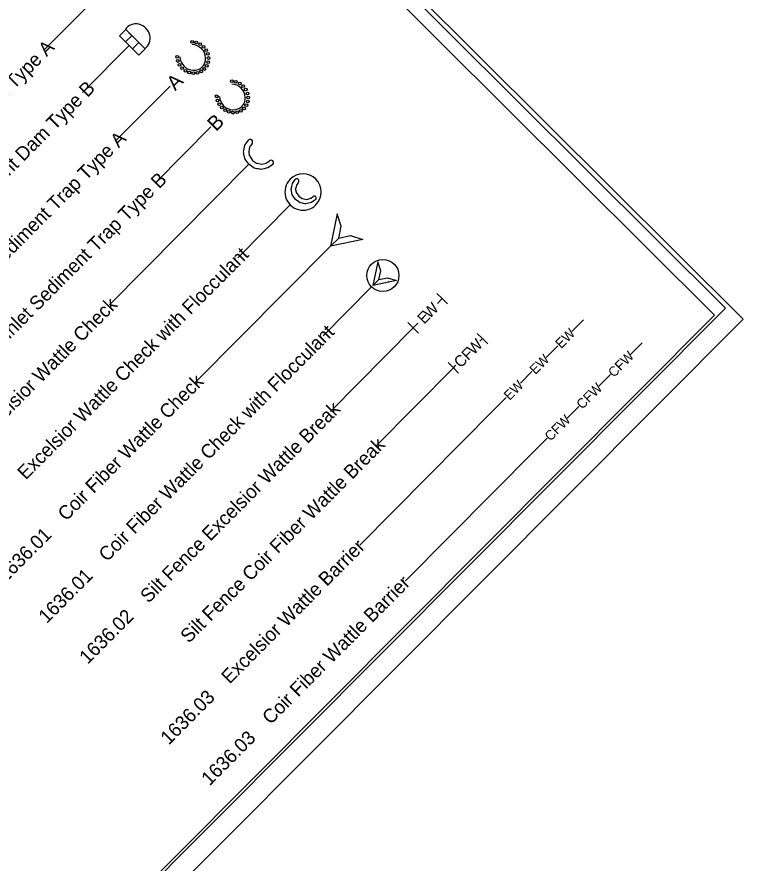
# Model space of a CAD drawing. Extents: x 1489771 to 1495672, y 500348 to 506262.
# Drawn here: x 1493531 to 1495672, y 502337 to 504832 of the extents above; entities that cross this region are included whole.
import ezdxf

# ---------------------------------------------------------------- set-up
doc = ezdxf.new("R2010")
doc.units = 0
for name, color, linetype in [('Old_Level_1', 7, 'Continuous'), ('Old_Level_12', 7, 'Continuous'), ('Sheet Plot Border Inside CELL', 7, 'Continuous')]:
    doc.layers.add(name, color=color, linetype=linetype)

msp = doc.modelspace()

# ---------------------------------------------------------------- linework, layer by layer
at = {"layer": 'Old_Level_1'}
for p, q in [((1493610.4, 504733.7), (1493742.9, 504867.2)), ((1493890.8, 504719.4), (1493833.7, 504776.3)), ((1493890.8, 504719.4), (1493833.7, 504776.3)), ((1493909.1, 504737.8), (1493852, 504794.7)), ((1493909.1, 504737.8), (1493852, 504794.7)), ((1493725, 504609.7), (1493862.2, 504747.8)), ((1493909.1, 504737.8), (1493890.8, 504719.4)), ((1493909.1, 504737.8), (1493890.8, 504719.4)), ((1493821.4, 504465.3), (1493982.8, 504627.8)), ((1493940.9, 504344.2), (1494103.3, 504507.7)), ((1494219.9, 504452.2), (1494217.4, 504448.6)), ((1494224.8, 504459.2), (1494219.9, 504452.2)), ((1494216.2, 504442.6), (1494214.6, 504434.7)), ((1494214.9, 504433.4), (1494214.6, 504434.7)), ((1494214.9, 504433.4), (1494216.3, 504427.5)), ((1494217.4, 504448.6), (1494216.2, 504442.6)), ((1494217.8, 504421), (1494216.3, 504427.5)), ((1494217.8, 504421), (1494226.2, 504409.1)), ((1494226.2, 504409.1), (1494226.2, 504409.1)), ((1494226.2, 504409.1), (1494237.7, 504401)), ((1494267.1, 504401.7), (1494275.6, 504407.5)), ((1493803.8, 503983.3), (1494214.6, 504397.5)), ((1494237.7, 504401), (1494244.2, 504399.5)), ((1494244.2, 504399.5), (1494252, 504397.7)), ((1494252, 504397.7), (1494257.6, 504398.9)), ((1494257.6, 504398.9), (1494265.6, 504400.6)), ((1494267.1, 504401.7), (1494265.6, 504400.6)), ((1494354, 504331.2), (1494352.7, 504324.7)), ((1494355, 504336.2), (1494354, 504331.2)), ((1494357.1, 504339.2), (1494355, 504336.2)), ((1494361.2, 504345.1), (1494357.1, 504339.2)), ((1494352.9, 504323.6), (1494352.7, 504324.7)), ((1494352.9, 504323.6), (1494354.1, 504318.6)), ((1494355.4, 504313.3), (1494354.1, 504318.6)), ((1494355.4, 504313.3), (1494362.4, 504303.3)), ((1494362.4, 504303.3), (1494362.4, 504303.3)), ((1494362.4, 504303.3), (1494372, 504296.5)), ((1494182.2, 504121.2), (1494337, 504277.7)), ((1494372, 504296.5), (1494377.4, 504295.2)), ((1494377.4, 504295.2), (1494383.9, 504293.7)), ((1494383.9, 504293.7), (1494388.5, 504294.8)), ((1494388.5, 504294.8), (1494395.2, 504296.2)), ((1494396.5, 504297.1), (1494395.2, 504296.2)), ((1494396.5, 504297.1), (1494403.6, 504301.9)), ((1494475.4, 504242.5), (1494475.4, 504242.5)), ((1494056.9, 503754.4), (1494456, 504155.9)), ((1494595, 504103.5), (1494595, 504103.5)), ((1494434, 503892), (1494576.6, 504035.9)), ((1494627.5, 504052.5), (1494626.5, 504051.8)), ((1494784.8, 504001.3), (1494769.3, 504016.8)), ((1494770.9, 503987.3), (1494784.8, 504001.3)), ((1494784.8, 504001.3), (1494800.4, 503985.8)), ((1494699.3, 503915.4), (1494683.7, 503930.9)), ((1494699.3, 503915.4), (1494713.2, 503929.4)), ((1495167.6, 503904.4), (1495201.7, 503938.8)), ((1494455.3, 503668.3), (1494699.3, 503915.4)), ((1494699.3, 503915.4), (1494714.8, 503899.9)), ((1494903.5, 503883.3), (1494887.9, 503898.8)), ((1494895.7, 503875.5), (1494903.5, 503883.3)), ((1494903.5, 503883.3), (1494919.1, 503867.8)), ((1495091.5, 503828), (1495125.7, 503862.3)), ((1495340.4, 503836.9), (1495374.6, 503871.3)), ((1494817.9, 503797.3), (1494802.3, 503812.8)), ((1494817.9, 503797.3), (1494825.6, 503805.1)), ((1494588.2, 503565.5), (1494817.9, 503797.3)), ((1494817.9, 503797.3), (1494833.5, 503781.8)), ((1495015.5, 503751.5), (1495049.6, 503785.9)), ((1495247, 503742.9), (1495281.1, 503777.3)), ((1494939.4, 503675.1), (1494973.6, 503709.5)), ((1495153.5, 503649), (1495187.6, 503683.4)), ((1494541.7, 503274.6), (1494939.4, 503675.1)), ((1495060, 503555), (1495094.2, 503589.4)), ((1494676.6, 503169.1), (1495060, 503555))]:
    msp.add_line(p, q, dxfattribs=at)
for points in [[(1493352.5, 506178.3), (1490172.1, 502984.8), (1492407.6, 500758.5), (1495587.9, 503952.1)], [(1493833.7, 504776.3), (1493852, 504794.7), (1493870, 504776.7), (1493851.7, 504758.3)], [(1493872.1, 504738), (1493890.5, 504756.4), (1493909.1, 504737.8), (1493890.8, 504719.4)], [(1494475.4, 504251.3), (1494456, 504155.9), (1494480, 504180), (1494487.3, 504214.6)], [(1494551.3, 504175.7), (1494456, 504155.9), (1494480, 504180), (1494514.6, 504187.4)], [(1494595, 504109.9), (1494580.8, 504040), (1494598.4, 504057.6), (1494603.7, 504083)], [(1494650.7, 504054.4), (1494580.8, 504040), (1494598.4, 504057.6), (1494623.7, 504063.1)]]:
    msp.add_lwpolyline(points, close=True, dxfattribs=at)
for points in [[(1494285.7, 504397.3), (1494278.7, 504392.4), (1494270.5, 504386.6), (1494266, 504385.6), (1494260.5, 504384.4), (1494250.8, 504382.2), (1494250.6, 504382.2), (1494248.2, 504382.7), (1494247.8, 504382.8), (1494242.6, 504383.9), (1494239, 504384.6), (1494231.1, 504386.3), (1494226.3, 504389.5), (1494214.6, 504397.4), (1494214.6, 504397.5), (1494206.4, 504409.5), (1494203.2, 504414.2), (1494201.9, 504420.4), (1494201.6, 504421.7), (1494200.6, 504426.9), (1494199.8, 504430.8), (1494199.6, 504431.8), (1494199.2, 504433.7), (1494199.2, 504433.8), (1494200.9, 504442), (1494202.5, 504449.2), (1494203.4, 504453.6), (1494208.8, 504461.7), (1494213.6, 504468.8)], [(1494412.1, 504293.5), (1494406.2, 504289.3), (1494399.3, 504284.5), (1494395.6, 504283.6), (1494391, 504282.6), (1494382.9, 504280.8), (1494382.7, 504280.9), (1494380.7, 504281.3), (1494380.4, 504281.3), (1494376.1, 504282.2), (1494373.1, 504282.9), (1494366.4, 504284.3), (1494362.5, 504286.9), (1494352.7, 504293.6), (1494352.7, 504293.6), (1494345.8, 504303.6), (1494343.1, 504307.6), (1494342.1, 504312.7), (1494341.9, 504313.8), (1494341, 504318.1), (1494340.3, 504321.4), (1494340.1, 504322.2), (1494339.8, 504323.8), (1494339.8, 504323.9), (1494341.3, 504330.7), (1494342.6, 504336.8), (1494343.3, 504340.4), (1494347.9, 504347.2), (1494351.8, 504353.1)]]:
    msp.add_lwpolyline(points, dxfattribs=at)
msp.add_circle((1494610.1, 504069.5), 47.4, dxfattribs=at)
for centre, radius, start, end in [((1494218.8, 504463.6), 7.38, 324.006, 135.1186), ((1494280.7, 504402.4), 7.18, 315.1186, 135.1186), ((1494374.8, 504315.7), 53.6, 135.1186, 315.1186), ((1494374.8, 504315.7), 53.6, 315.1186, 135.1186), ((1494356.2, 504348.7), 6.16, 324.006, 135.1186), ((1494407.8, 504297.7), 5.99, 315.1186, 135.1186)]:
    msp.add_arc(centre, radius, start, end, dxfattribs=at)
for centre, major_axis, start_param, end_param in [((1493884.8, 504771.8), (-29.1, 29), 2.949905, 6.474869), ((1493884.8, 504771.8), (-29.1, 29), 2.949905, 6.474869), ((1494049.7, 504712.6), (-27.9, 27.8), 0.785389, 5.497624), ((1494166.5, 504596.2), (-27.9, 27.8), 0.785389, 5.497624)]:
    msp.add_ellipse(centre, major_axis=major_axis, ratio=0.927398, start_param=start_param, end_param=end_param, dxfattribs=at)
for centre, major_axis in [((1494047.9, 504758.9), (-3.01, 3)), ((1494059.9, 504756.9), (-3.01, 3)), ((1494071.3, 504751.8), (-3.01, 3)), ((1494081.1, 504744.2), (-3.01, 3)), ((1494088.9, 504734.3), (-3.01, 3)), ((1494093.9, 504723), (-3.01, 3)), ((1494003.4, 504714.2), (3.01, -3)), ((1494005.4, 504702.2), (3.01, -3)), ((1494094.9, 504699), (3.01, -3)), ((1494096, 504710.9), (-3.01, 3)), ((1494010.5, 504690.9), (3.01, -3)), ((1494018.2, 504681), (3.01, -3)), ((1494028.1, 504673.3), (3.01, -3)), ((1494083.7, 504678.7), (3.01, -3)), ((1494090.7, 504688), (3.01, -3)), ((1494039.5, 504668.3), (3.01, -3)), ((1494051.5, 504666.3), (3.01, -3)), ((1494063.4, 504667.4), (3.01, -3)), ((1494074.4, 504671.7), (3.01, -3)), ((1494164.7, 504642.5), (-3.01, 3)), ((1494176.7, 504640.5), (-3.01, 3)), ((1494188.1, 504635.5), (-3.01, 3)), ((1494198, 504627.8), (-3.01, 3)), ((1494120.2, 504597.9), (3.01, -3)), ((1494205.7, 504617.9), (-3.01, 3)), ((1494210.8, 504606.6), (-3.01, 3)), ((1494122.3, 504585.8), (3.01, -3)), ((1494127.4, 504574.5), (3.01, -3)), ((1494211.7, 504582.6), (3.01, -3)), ((1494212.8, 504594.6), (-3.01, 3)), ((1494135.1, 504564.7), (3.01, -3)), ((1494145, 504557), (3.01, -3)), ((1494156.3, 504551.9), (3.01, -3)), ((1494168.4, 504549.9), (3.01, -3)), ((1494180.3, 504551.1), (3.01, -3)), ((1494191.3, 504555.3), (3.01, -3)), ((1494200.6, 504562.3), (3.01, -3)), ((1494207.6, 504571.6), (3.01, -3))]:
    msp.add_ellipse(centre, major_axis=major_axis, ratio=0.927398, dxfattribs=at)
at = {"layer": 'Old_Level_12'}
msp.add_lwpolyline([(1492102.5, 500356.3), (1495671.9, 503940.6), (1493340.6, 506262.2), (1489771.2, 502678)], close=True, dxfattribs=at)
at = {"layer": 'Sheet Plot Border Inside CELL'}
msp.add_lwpolyline([(1492087.5, 500426.4), (1495619.8, 503973.4), (1493373.6, 506210.2), (1489841.3, 502663.3)], close=True, dxfattribs=at)

# ---------------------------------------------------------------- texts
at = {"layer": 'Old_Level_1'}
for s, height, p in [('Temporary Rock Sediment Dam Type A', 40.777, (1492962.4, 504054.1)), ('A', 42.9, (1493998, 504612.6)), ('Temporary Rock Sediment Dam Type B', 40.761, (1493082.6, 503933.9)), ('B', 42.9, (1494118.5, 504492.6)), ('Rock Pipe Inlet Sediment Trap Type A', 40.704, (1493203.4, 503814.1)), ('Rock Pipe Inlet Sediment Trap Type B', 40.704, (1493322.9, 503693)), ('Excelsior Wattle Check with Flocculant', 40.761, (1493557.3, 503464.8)), ('Excelsior Wattle Check', 40.761, (1493435.1, 503583.3)), ('W', 33.1, (1494748, 503940.3)), ('E', 33.1, (1494731.7, 503924)), ('Coir Fiber Wattle Check with Flocculant', 40.761, (1493796.8, 503223.2)), ('EW', 28.58, (1495135.8, 503852.3)), ('W', 33.1, (1494877.8, 503833.4)), ('F', 33.1, (1494861.5, 503817.1)), ('C', 33.1, (1494839.3, 503794.9)), ('EW', 28.58, (1495059.8, 503775.8)), ('CFW', 28.58, (1495291.2, 503767.2)), ('Coir Fiber Wattle Check', 40.761, (1493676.2, 503343.2)), ('EW', 28.58, (1494983.7, 503699.4)), ('CFW', 28.58, (1495197.8, 503673.3)), ('Silt Fence Excelsior Wattle Break', 40.777, (1493919.3, 503101.2)), ('CFW', 28.58, (1495104.3, 503579.3)), ('Silt Fence Coir Fiber Wattle Break', 40.777, (1494037.9, 502983.1)), ('1636.01', 40.71, (1493497.8, 503162.2)), ('Excelsior Wattle Barrier', 40.777, (1494158.4, 502863)), ('1636.01', 40.71, (1493619.3, 503041.2)), ('Coir Fiber Wattle Barrier', 40.777, (1494279, 502743)), ('1636.02', 40.71, (1493739.8, 502921.1)), ('1636.03', 40.71, (1493979, 502683)), ('1636.03', 40.71, (1494099.5, 502562.9))]:
    msp.add_text(s, height=height, rotation=45.1186, dxfattribs=at).set_placement(p)

doc.saveas('drawing.dxf')
